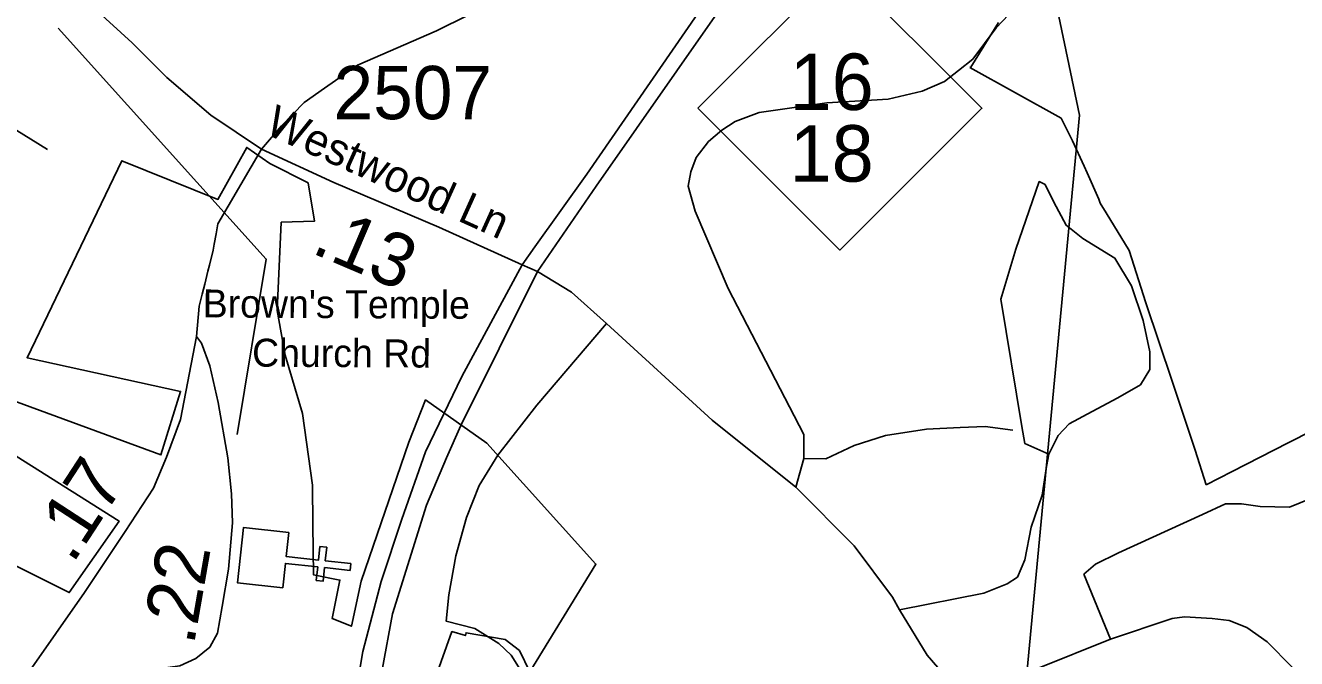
# Model space of a CAD drawing. Extents: x 1248089 to 1457196, y 820910 to 988753.
# Drawn here: x 1359357 to 1362337, y 872834 to 874320 of the extents above; entities that cross this region are included whole.
import ezdxf

# ---------------------------------------------------------------- set-up
doc = ezdxf.new("R2010")
doc.units = 0
for name, color, linetype in [('Exist Boundary Political City Limit New', 7, 'Continuous'), ('Exist Boundary Political City Limit New Hole', 7, 'Continuous'), ('Exist Cultural Church CELL', 7, 'Continuous'), ('Exist Road Non-System Type 51', 7, 'Continuous'), ('Exist Road Primary NC Divided Attributed', 7, 'Continuous'), ('Exist Road Primary NC Shield CELL', 7, 'Continuous'), ('Exist Road Primary NC Shield Number Label', 7, 'Continuous'), ('Exist Road Primary NC Structure Ovrhead Sign Number Label', 7, 'Continuous'), ('Exist Road Secondary Type 51 Attributed', 7, 'Continuous'), ('Exist Road Secondary Type 51 Label', 7, 'Continuous'), ('Map Preparation Boundary City Limit Buffer Line', 7, 'Continuous'), ('Prop GRAU CAT1 Cell', 7, 'Continuous'), ('Prop Lane Lines', 7, 'Continuous')]:
    doc.layers.add(name, color=color, linetype=linetype)

msp = doc.modelspace()

# ---------------------------------------------------------------- linework, layer by layer
at = {"layer": 'Exist Boundary Political City Limit New'}
for points in [[(1360240.5, 872570), (1360357.1, 872897.7), (1360388.6, 872888.4), (1360390.3, 872895.2), (1360482, 872879), (1360515.3, 872853.1), (1360539.6, 872803.7), (1360694.8, 873056.1), (1360439.1, 873339.3), (1360295.3, 873441.3), (1360256.3, 873342.3), (1360144.2, 873015.9), (1360121.5, 872910.4), (1360076.5, 872928.4), (1360094.5, 873018.4), (1360033, 873030.7), (1360031.2, 873147.9), (1360030, 873241.5), (1360007.1, 873409.1), (1359966.3, 873546.3), (1359947.5, 873650.6), (1359956.9, 873857.7), (1360034.8, 873860.3), (1360019.9, 873950.3), (1359930, 873995.3), (1359876.1, 874033.5), (1359808.6, 873911.5), (1359583, 874002), (1359361.1, 873539.9), (1359721, 873461), (1359675.1, 873312.2), (1359315, 873444.3)], [(1359260.4, 873356.3), (1359577.1, 873157.1), (1359460.1, 872989.2), (1359305.1, 873067.2)]]:
    msp.add_lwpolyline(points, dxfattribs=at)
at = {"layer": 'Exist Boundary Political City Limit New Hole'}
for p, q in [((1361571.3, 874220.9), (1361785.3, 874101.9)), ((1362099, 873323.1), (1362125.4, 873242.3)), ((1362125.4, 873242.3), (1362186.2, 873272.9))]:
    msp.add_line(p, q, dxfattribs=at)
for points in [[(1361638.5, 874326.3), (1361573.2, 874221.8), (1361571.3, 874220.9)], [(1361785.3, 874101.9), (1361811.9, 874048.6), (1361838.9, 873989.7)], [(1361838.9, 873989.7), (1361846.1, 873973.7), (1361873.5, 873911.8), (1361876.9, 873902.3), (1361890.5, 873879.9), (1361944.8, 873791.4), (1361983.7, 873668.7), (1362045.6, 873485), (1362099, 873323.1)], [(1362186.2, 873272.9), (1362317.1, 873340.8), (1362431.1, 873398.5), (1362534.6, 873450.9), (1362570.8, 873469.3), (1362572.1, 873466.4)]]:
    msp.add_lwpolyline(points, dxfattribs=at)
at = {"layer": 'Exist Cultural Church CELL'}
msp.add_lwpolyline([(1359974.8, 873130.3), (1359968.7, 873073.7), (1360044.4, 873065.5), (1360047.9, 873097.3), (1360063.8, 873095.6), (1360060.3, 873063.8), (1360120.1, 873057.3), (1360118.4, 873041.4), (1360058.6, 873047.9), (1360055.1, 873016), (1360039.2, 873017.8), (1360042.7, 873049.6), (1359967, 873057.8), (1359960.7, 873000.5), (1359854.8, 873012), (1359868.9, 873141.9)], close=True, dxfattribs=at)
at = {"layer": 'Exist Road Non-System Type 51'}
for points in [[(1359910.8, 874029.2), (1359791.8, 874108.8), (1359688.7, 874197.2), (1359607.7, 874278.3), (1359519.3, 874359.4), (1359437, 874453.4), (1359411.2, 874498.8), (1359385.5, 874565.2), (1359374.4, 874620.5)], [(1360617.9, 874454.3), (1360320.9, 874307.1), (1360135.8, 874226.4), (1360058.5, 874172.3), (1360010.6, 874139.1), (1359957.8, 874083.8), (1359910.8, 874029.2)], [(1361163.1, 873236.6), (1361181.9, 873303.5), (1361181.9, 873359.9), (1361148.5, 873424.6), (1361004.5, 873702.4), (1360927.3, 873884.1), (1360910.6, 873942.6), (1360916.9, 873976), (1360929.4, 874009.4), (1360958.6, 874047), (1360989.8, 874073.5), (1361021.1, 874094.3), (1361077.4, 874115.2), (1361236, 874138.2), (1361380, 874146.6), (1361459.3, 874165.3), (1361511.5, 874188.3), (1361544.9, 874213.4), (1361578.3, 874240.5), (1361632.6, 874313.6), (1361661.6, 874344.2)], [(1359151.2, 874224.5), (1359199.2, 874169.5), (1359233.6, 874137.6), (1359314.6, 874087.2), (1359408.8, 874028.4)], [(1361756.1, 873313.6), (1361699.8, 873339.2), (1361693, 873378.5), (1361643.5, 873677.2), (1361679.3, 873795), (1361733.8, 873953.1), (1361747.5, 873946.3), (1361767.9, 873905.3), (1361796.9, 873850.7), (1361836.2, 873820), (1361911.2, 873773.9), (1361950.4, 873709), (1361977.7, 873627.1), (1361993.1, 873553.7), (1361993.1, 873512.7), (1361970.9, 873476.9), (1361918, 873446.1), (1361858.3, 873413.7)], [(1360557.9, 873742.7), (1360637.8, 873693.8), (1360719.2, 873620.7)], [(1360719.2, 873620.7), (1360556.4, 873428.5), (1360464.6, 873311.6), (1360420.8, 873240.6), (1360391.6, 873165.4), (1360366.5, 873075.6), (1360349.8, 872983.7), (1360343.7, 872921.9), (1360410.5, 872905.2), (1360466.9, 872869.7), (1360496.1, 872842.6), (1360525.3, 872796.6), (1360562.9, 872721.4), (1360577.5, 872637.9), (1360573.3, 872566.9)], [(1360719.2, 873620.7), (1360967, 873393.3), (1361163.1, 873236.6)], [(1361858.3, 873413.7), (1361803.8, 873384.7), (1361778.2, 873357.4), (1361756.1, 873313.6)], [(1361671.7, 873370.1), (1361607, 873378.4), (1361548.6, 873376.3), (1361469.3, 873372.2), (1361373.3, 873357.5), (1361300.2, 873334.6), (1361233.5, 873303.2), (1361181.9, 873303.5)], [(1361406.7, 872948.9), (1361604.3, 872987.6), (1361658.8, 873009.8), (1361682.7, 873025.2), (1361699.8, 873066.1), (1361715.1, 873142.9), (1361740.7, 873218), (1361750.9, 873284.6), (1361756.1, 873313.6)], [(1361838.6, 873032.6), (1361865.7, 873055.5), (1361920, 873082.7), (1362116.2, 873172.5), (1362170.4, 873197.5), (1362208, 873197.5), (1362251.8, 873191.3), (1362320.7, 873189.2), (1362370.8, 873210.1), (1362439.7, 873239.3), (1362464.7, 873251.9), (1362512.7, 873270.6), (1362558.6, 873268.6), (1362585.8, 873239.3), (1362592, 873224.7)], [(1361163.1, 873236.6), (1361300.3, 873099.2), (1361390, 872978.1), (1361406.7, 872948.9)], [(1361901.2, 872880.1), (1361838.6, 873032.6)], [(1361406.7, 872948.9), (1361471.3, 872842.5), (1361496.3, 872813.3), (1361531.8, 872790.3), (1361546.4, 872781.9)], [(1361901.2, 872880.1), (1362045.2, 872928.1), (1362074.4, 872932.3), (1362139.1, 872928.1), (1362178.8, 872924), (1362220.5, 872907.2), (1362268.5, 872873.8), (1362385.4, 872754.8), (1362541.9, 872575.2), (1362858.5, 872344.4), (1362958.7, 872254.6), (1363017.2, 872198.2)], [(1361546.4, 872781.9), (1361588.2, 872775.7), (1361640.3, 872777.8), (1361730.1, 872811.2), (1361901.2, 872880.1)]]:
    msp.add_lwpolyline(points, dxfattribs=at)
at = {"layer": 'Exist Road Primary NC Divided Attributed'}
for points in [[(1361545.9, 875241.5), (1361297.2, 874876.5), (1361022.5, 874477.5), (1360673.4, 873970.4), (1360551.7, 873800.3), (1360521.9, 873757.8)], [(1360557.9, 873742.7), (1360695.3, 873942.5), (1360978.6, 874347.9), (1361172.2, 874634.2), (1361307.6, 874830.5)], [(1359910.5, 870731), (1360006.7, 871396), (1360042.9, 871616.1), (1360061, 871783.3), (1360127.7, 872330.8), (1360169.5, 872676.4), (1360218, 872939.1), (1360297.3, 873194.3), (1360344.6, 873305.2), (1360377.7, 873381.4), (1360557.9, 873742.7)], [(1360521.9, 873757.8), (1360380.7, 873496.2), (1360294.9, 873319.2), (1360239.8, 873161.4), (1360191.4, 873015.3), (1360148.4, 872850.8), (1360130.7, 872743.7), (1360085.6, 872371.5), (1360067.9, 872265.5), (1360001.5, 871704.9), (1359921.7, 871095.6)]]:
    msp.add_lwpolyline(points, dxfattribs=at)
at = {"layer": 'Exist Road Primary NC Shield CELL'}
msp.add_lwpolyline([(1360933.4, 874125.4), (1361266.4, 874458.4), (1361599.4, 874125.4), (1361266.4, 873792.4)], close=True, dxfattribs=at)
at = {"layer": 'Exist Road Primary NC Structure Ovrhead Sign Number Label'}
msp.add_lwpolyline([(1361615, 875129.2), (1361828.1, 874109), (1361660.6, 872327.4)], dxfattribs=at)
at = {"layer": 'Exist Road Secondary Type 51 Attributed'}
for points in [[(1359758.7, 873589.8), (1359764.9, 873661.3), (1359771.5, 873689.1), (1359778, 873713), (1359784.6, 873742.9), (1359788.9, 873756.8), (1359797.6, 873792.7), (1359799.9, 873806.7), (1359804.4, 873830.6), (1359808.8, 873854.5), (1359910.8, 874029.2)], [(1359910.8, 874029.2), (1360080.7, 873950.9), (1360326.7, 873846), (1360521.9, 873757.8)], [(1360521.9, 873757.8), (1360557.9, 873742.7)], [(1359361.7, 872797.2), (1359496.2, 872989.3), (1359591.1, 873132.8), (1359657.3, 873234.3), (1359688.1, 873307.2), (1359721.2, 873395.5), (1359758.7, 873589.8)], [(1359758.7, 873589.8), (1359769.8, 873574.3), (1359789.6, 873521.3), (1359809.5, 873435.2), (1359831.5, 873305), (1359840.3, 873221.1), (1359842.5, 873152.6), (1359833.7, 873044.5), (1359818.3, 872956.4)], [(1359818.3, 872956.4), (1359807.3, 872894.4), (1359789.6, 872861.2), (1359756.5, 872834.7), (1359719, 872817.1), (1359668.3, 872810.5), (1359610.9, 872808.3), (1359511.7, 872795), (1359427.3, 872786.8)]]:
    msp.add_lwpolyline(points, dxfattribs=at)
at = {"layer": 'Map Preparation Boundary City Limit Buffer Line'}
for points in [[(1360240.5, 872570), (1360357.1, 872897.7), (1360388.6, 872888.4), (1360390.3, 872895.2), (1360482, 872879), (1360515.3, 872853.1), (1360539.6, 872803.7), (1360694.8, 873056.1), (1360439.1, 873339.3), (1360295.3, 873441.3), (1360256.3, 873342.3), (1360144.2, 873015.9), (1360121.5, 872910.4), (1360076.5, 872928.4), (1360094.5, 873018.4), (1360033, 873030.7), (1360031.2, 873147.9), (1360030, 873241.5), (1360007.1, 873409.1), (1359966.3, 873546.3), (1359947.5, 873650.6), (1359956.9, 873857.7), (1360034.8, 873860.3), (1360019.9, 873950.3), (1359930, 873995.3), (1359876.1, 874033.5), (1359808.6, 873911.5), (1359583, 874002), (1359361.1, 873539.9), (1359721, 873461), (1359675.1, 873312.2), (1359315, 873444.3)], [(1359260.4, 873356.3), (1359577.1, 873157.1), (1359460.1, 872989.2), (1359305.1, 873067.2)]]:
    msp.add_lwpolyline(points, dxfattribs=at)
at = {"layer": 'Prop Lane Lines'}
msp.add_lwpolyline([(1359853.5, 873359.7), (1359922.1, 873771.5), (1359434.1, 874312.8)], dxfattribs=at)

# ---------------------------------------------------------------- texts
at = {"layer": 'Exist Road Primary NC Shield Number Label'}
for s, p in [('16', (1361148.8, 874121.1)), ('18', (1361148.8, 873953))]:
    msp.add_text(s, height=132.5, dxfattribs=at).set_placement(p)
at = {"layer": 'Exist Road Secondary Type 51 Label'}
for s, height, rotation, p in [('Westwood Ln', 75, 335.7185, (1359915.6, 874066.8)), ("Brown's Temple ", 65.617, 359.6978, (1359772.8, 873634.6)), ('Church Rd', 65.62, 359.6978, (1359888.6, 873519.2))]:
    msp.add_text(s, height=height, rotation=rotation, dxfattribs=at).set_placement(p)
at = {"layer": 'Prop GRAU CAT1 Cell'}
for s, rotation, p in [('.13', 336.9091, (1360024.6, 873787.1)), ('.17', 56.9096, (1359468.1, 873054.5)), ('.22', 80.0811, (1359752.1, 872863.8))]:
    msp.add_text(s, height=125, rotation=rotation, dxfattribs=at).set_placement(p)
at = {"layer": 'Prop Lane Lines'}
msp.add_text('2507', height=125, dxfattribs=at).set_placement((1360079.4, 874099.5))

doc.saveas('drawing.dxf')
